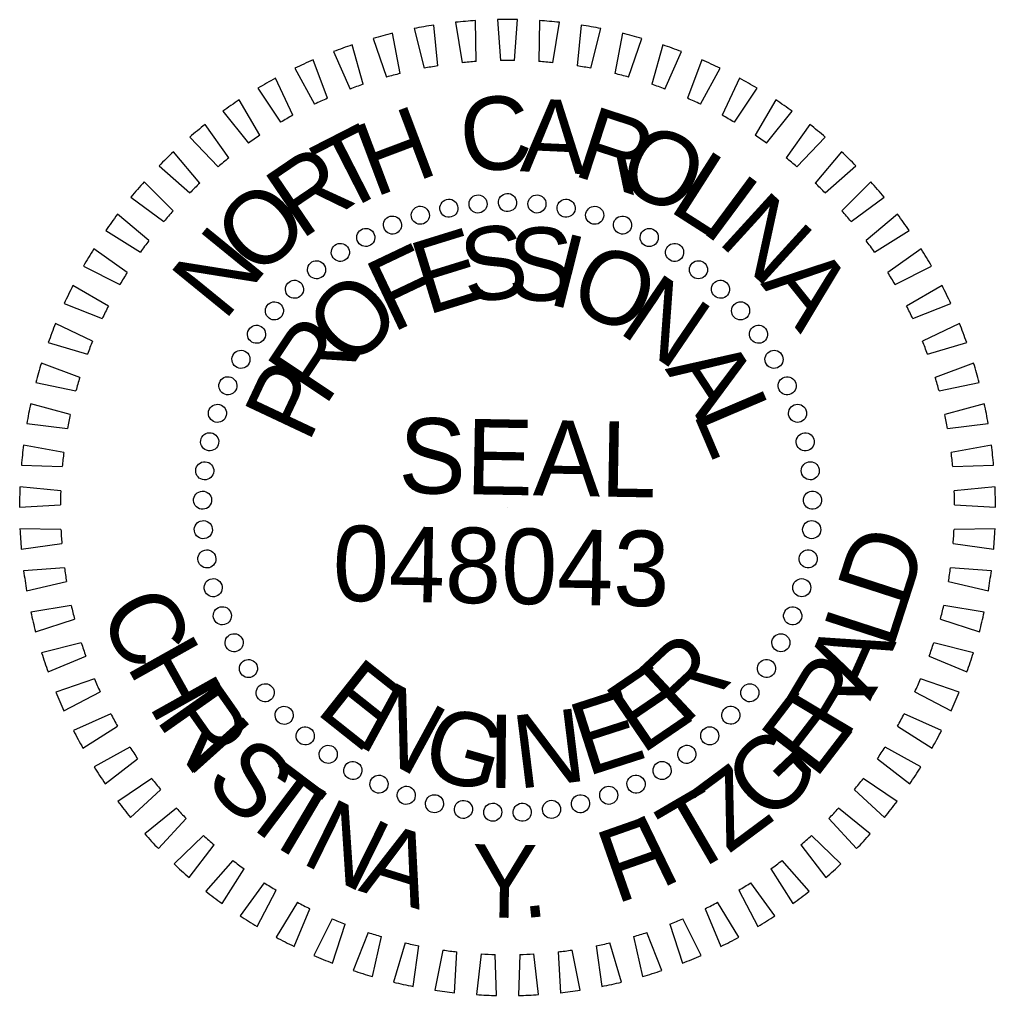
# Model space of a CAD drawing. Extents: x 2044664 to 2046614, y 755540 to 756566.
# Drawn here: x 2046310.5 to 2046390.5, y 756451.5 to 756531.5 of the extents above; entities that cross this region are included whole.
import ezdxf

# ---------------------------------------------------------------- set-up
doc = ezdxf.new("R2010")
doc.units = 0
doc.layers.add('Sheet PE Seal Cell', color=7, linetype='Continuous')

msp = doc.modelspace()

# ---------------------------------------------------------------- linework, layer by layer
at = {"layer": 'Sheet PE Seal Cell'}
for p, q in [((2046344.826, 756527.666), (2046344.499, 756531.005)), ((2046346.276, 756531.236), (2046346.813, 756527.924)), ((2046347.959, 756528.023), (2046347.92, 756531.378)), ((2046349.711, 756531.455), (2046349.961, 756528.109)), ((2046351.111, 756528.109), (2046351.361, 756531.455)), ((2046353.152, 756531.378), (2046353.114, 756528.023)), ((2046354.259, 756527.924), (2046354.796, 756531.236)), ((2046356.574, 756531.005), (2046356.247, 756527.666)), ((2046341.735, 756527.041), (2046341.122, 756530.34)), ((2046342.873, 756530.723), (2046343.693, 756527.469)), ((2046357.38, 756527.469), (2046358.199, 756530.723)), ((2046359.95, 756530.34), (2046359.338, 756527.041)), ((2046338.709, 756526.153), (2046337.815, 756529.387)), ((2046339.527, 756529.918), (2046340.623, 756526.747)), ((2046360.45, 756526.747), (2046361.546, 756529.918)), ((2046363.258, 756529.387), (2046362.364, 756526.153)), ((2046336.262, 756528.83), (2046337.626, 756525.764)), ((2046363.446, 756525.764), (2046364.811, 756528.83)), ((2046335.77, 756525.007), (2046334.602, 756528.153)), ((2046366.471, 756528.153), (2046365.302, 756525.007)), ((2046333.102, 756527.464), (2046334.725, 756524.528)), ((2046366.347, 756524.528), (2046367.97, 756527.464)), ((2046332.942, 756523.614), (2046331.507, 756526.647)), ((2046369.566, 756526.647), (2046368.131, 756523.614)), ((2046330.072, 756525.832), (2046331.942, 756523.046)), ((2046369.131, 756523.046), (2046371, 756525.832)), ((2046330.243, 756521.982), (2046328.553, 756524.881)), ((2046372.52, 756524.881), (2046370.829, 756521.982)), ((2046327.193, 756523.946), (2046329.295, 756521.331)), ((2046371.777, 756521.331), (2046373.879, 756523.946)), ((2046327.694, 756520.125), (2046325.761, 756522.867)), ((2046375.311, 756522.867), (2046373.378, 756520.125)), ((2046324.487, 756521.819), (2046326.806, 756519.394)), ((2046374.266, 756519.394), (2046376.585, 756521.819)), ((2046325.315, 756518.055), (2046323.153, 756520.621)), ((2046377.919, 756520.621), (2046375.757, 756518.055)), ((2046321.974, 756519.467), (2046324.493, 756517.251)), ((2046376.579, 756517.251), (2046379.098, 756519.467)), ((2046323.123, 756515.789), (2046320.748, 756518.159)), ((2046380.324, 756518.159), (2046377.95, 756515.789)), ((2046319.673, 756516.908), (2046322.373, 756514.917)), ((2046378.7, 756514.917), (2046381.4, 756516.908)), ((2046321.133, 756513.342), (2046318.564, 756515.5)), ((2046382.509, 756515.5), (2046379.939, 756513.342)), ((2046317.599, 756514.161), (2046320.461, 756512.409)), ((2046380.611, 756512.409), (2046383.473, 756514.161)), ((2046319.361, 756510.733), (2046316.616, 756512.662)), ((2046384.457, 756512.662), (2046381.711, 756510.733)), ((2046315.77, 756511.245), (2046318.772, 756509.746)), ((2046382.301, 756509.746), (2046385.302, 756511.245)), ((2046317.82, 756507.982), (2046314.919, 756509.668)), ((2046386.154, 756509.668), (2046383.253, 756507.982)), ((2046314.198, 756508.184), (2046317.318, 756506.947)), ((2046383.755, 756506.947), (2046386.874, 756508.184)), ((2046316.521, 756505.108), (2046313.486, 756506.539)), ((2046387.587, 756506.539), (2046384.551, 756505.108)), ((2046312.896, 756504.998), (2046316.11, 756504.035)), ((2046384.963, 756504.035), (2046388.177, 756504.998)), ((2046315.474, 756502.134), (2046312.327, 756503.298)), ((2046388.745, 756503.298), (2046385.598, 756502.134)), ((2046311.871, 756501.712), (2046315.156, 756501.029)), ((2046385.916, 756501.029), (2046389.201, 756501.712)), ((2046314.686, 756499.08), (2046311.451, 756499.969)), ((2046389.621, 756499.969), (2046386.386, 756499.08)), ((2046311.133, 756498.35), (2046314.465, 756497.952)), ((2046386.607, 756497.952), (2046389.939, 756498.35)), ((2046314.164, 756495.97), (2046310.865, 756496.578)), ((2046390.208, 756496.578), (2046386.908, 756495.97)), ((2046310.687, 756494.938), (2046314.041, 756494.827)), ((2046387.032, 756494.827), (2046390.385, 756494.938)), ((2046313.912, 756492.827), (2046310.572, 756493.149)), ((2046390.501, 756493.149), (2046387.161, 756492.827)), ((2046310.536, 756491.499), (2046313.887, 756491.677)), ((2046350.536, 756491.463), (2046350.536, 756491.463)), ((2046387.186, 756491.677), (2046390.536, 756491.499)), ((2046313.93, 756489.673), (2046310.575, 756489.707)), ((2046390.498, 756489.707), (2046387.142, 756489.673)), ((2046310.681, 756488.06), (2046314.004, 756488.526)), ((2046387.068, 756488.526), (2046390.391, 756488.06)), ((2046314.219, 756486.533), (2046310.874, 756486.278)), ((2046390.199, 756486.278), (2046386.853, 756486.533)), ((2046311.121, 756484.647), (2046314.392, 756485.396)), ((2046386.68, 756485.396), (2046389.951, 756484.647)), ((2046314.778, 756483.429), (2046311.466, 756482.888)), ((2046389.606, 756482.888), (2046386.295, 756483.429)), ((2046311.853, 756481.284), (2046315.047, 756482.311)), ((2046386.025, 756482.311), (2046389.219, 756481.284)), ((2046315.601, 756480.385), (2046312.348, 756479.561)), ((2046388.724, 756479.561), (2046385.472, 756480.385)), ((2046312.871, 756477.996), (2046315.965, 756479.295)), ((2046385.107, 756479.295), (2046388.201, 756477.996)), ((2046316.682, 756477.423), (2046313.513, 756476.322)), ((2046387.56, 756476.322), (2046384.39, 756477.423)), ((2046314.169, 756474.808), (2046317.139, 756476.368)), ((2046383.933, 756476.368), (2046386.904, 756474.808)), ((2046318.015, 756474.565), (2046314.951, 756473.195)), ((2046386.121, 756473.195), (2046383.058, 756474.565)), ((2046315.735, 756471.743), (2046318.561, 756473.553)), ((2046382.512, 756473.553), (2046385.337, 756471.743)), ((2046319.588, 756471.832), (2046316.653, 756470.204)), ((2046384.419, 756470.204), (2046381.485, 756471.832)), ((2046317.559, 756468.825), (2046320.219, 756470.87)), ((2046380.853, 756470.87), (2046383.513, 756468.825)), ((2046321.39, 756469.244), (2046318.606, 756467.37)), ((2046382.466, 756467.37), (2046379.682, 756469.244)), ((2046319.627, 756466.074), (2046322.101, 756468.34)), ((2046378.971, 756468.34), (2046381.445, 756466.074)), ((2046323.408, 756466.82), (2046320.796, 756464.714)), ((2046380.277, 756464.714), (2046377.664, 756466.82)), ((2046321.924, 756463.511), (2046324.194, 756465.981)), ((2046376.878, 756465.981), (2046379.148, 756463.511)), ((2046325.627, 756464.58), (2046323.205, 756462.257)), ((2046377.867, 756462.257), (2046375.446, 756464.58)), ((2046324.433, 756461.154), (2046326.483, 756463.811)), ((2046374.59, 756463.811), (2046376.639, 756461.154)), ((2046328.03, 756462.538), (2046325.817, 756460.015)), ((2046375.255, 756460.015), (2046373.042, 756462.538)), ((2046327.135, 756459.023), (2046328.949, 756461.846)), ((2046372.124, 756461.846), (2046373.937, 756459.023)), ((2046330.6, 756460.71), (2046328.612, 756458.007)), ((2046372.46, 756458.007), (2046370.472, 756460.71)), ((2046330.011, 756457.131), (2046331.575, 756460.1)), ((2046369.498, 756460.1), (2046371.062, 756457.131)), ((2046333.317, 756459.11), (2046331.57, 756456.246)), ((2046369.503, 756456.246), (2046367.755, 756459.11)), ((2046333.038, 756455.494), (2046334.341, 756458.586)), ((2046366.731, 756458.586), (2046368.034, 756455.494)), ((2046336.162, 756457.75), (2046334.667, 756454.746)), ((2046336.195, 756454.123), (2046337.227, 756457.315)), ((2046363.845, 756457.315), (2046364.877, 756454.123)), ((2046366.405, 756454.746), (2046364.91, 756457.75)), ((2046339.114, 756456.639), (2046337.882, 756453.518)), ((2046363.19, 756453.518), (2046361.958, 756456.639)), ((2046339.458, 756453.028), (2046340.212, 756456.298)), ((2046342.15, 756455.786), (2046341.191, 756452.57)), ((2046359.881, 756452.57), (2046358.922, 756455.786)), ((2046360.86, 756456.298), (2046361.614, 756453.028)), ((2046342.803, 756452.218), (2046343.273, 756455.54)), ((2046345.248, 756455.197), (2046344.569, 756451.911)), ((2046346.205, 756451.699), (2046346.388, 756455.049)), ((2046354.684, 756455.049), (2046354.867, 756451.699)), ((2046356.503, 756451.911), (2046355.824, 756455.197)), ((2046357.799, 756455.54), (2046358.269, 756452.218)), ((2046348.385, 756454.877), (2046347.991, 756451.545)), ((2046349.64, 756451.474), (2046349.534, 756454.827)), ((2046351.538, 756454.827), (2046351.432, 756451.474)), ((2046353.081, 756451.545), (2046352.687, 756454.877))]:
    msp.add_line(p, q, dxfattribs=at)
for radius, start, end in [(40, 98.6812, 101.04482), (40, 93.7497, 96.11332), (40, 88.81819, 91.18181), (40, 83.88668, 86.2503), (40, 78.95518, 81.3188), (40, 103.61271, 105.97633), (40, 74.02367, 76.38729), (40, 108.54422, 110.90784), (40, 69.09216, 71.45578), (40, 113.47572, 115.83934), (36.65, 94.03256, 95.83045), (36.65, 89.10105, 90.89895), (36.65, 84.16955, 85.96744), (40, 64.16066, 66.52427), (36.65, 103.89557, 105.69347), (36.65, 98.96407, 100.76196), (36.65, 79.23804, 81.03593), (36.65, 74.30653, 76.10443), (40, 118.40723, 120.77085), (36.65, 108.82708, 110.62497), (36.65, 69.37503, 71.17292), (40, 59.22915, 61.59277), (40, 123.33874, 125.70236), (36.65, 113.75859, 115.55648), (36.65, 64.44352, 66.24141), (40, 54.29764, 56.66126), (36.65, 118.69009, 120.48799), (36.65, 59.51201, 61.30991), (40, 128.27025, 130.63386), (40, 49.36614, 51.72975), (36.65, 123.6216, 125.4195), (36.65, 54.5805, 56.3784), (40, 133.20175, 135.56537), (40, 44.43463, 46.79825), (36.65, 128.55311, 130.351), (36.65, 49.649, 51.44689), (40, 138.13326, 140.49688), (40, 39.50312, 41.86674), (36.65, 133.48461, 135.28251), (36.65, 44.71749, 46.51539), (36.65, 138.41612, 140.21402), (36.65, 39.78598, 41.58388), (40, 143.06477, 145.42838), (40, 34.57162, 36.93523), (36.65, 143.34763, 145.14552), (36.65, 34.85448, 36.65237), (40, 147.99627, 150.35989), (40, 29.64011, 32.00373), (36.65, 148.27913, 150.07703), (36.65, 29.92297, 31.72087), (40, 152.92778, 155.2914), (40, 24.7086, 27.07222), (36.65, 153.21064, 155.00854), (36.65, 24.99146, 26.78936), (40, 157.85929, 160.22291), (40, 19.77709, 22.14071), (36.65, 158.14215, 159.94004), (36.65, 20.05996, 21.85785), (40, 162.79079, 165.15441), (40, 14.84559, 17.20921), (36.65, 163.07366, 164.87155), (36.65, 15.12845, 16.92634), (40, 167.7223, 170.08592), (40, 9.91408, 12.2777), (36.65, 168.00516, 169.80306), (36.65, 10.19694, 11.99484), (40, 172.65381, 175.01743), (40, 4.98257, 7.34619), (36.65, 172.93667, 174.73456), (36.65, 5.26544, 7.06333), (40, 177.58531, 179.94893), (36.65, 177.86818, 179.66607), (36.65, 0.33393, 2.13182), (40, 0.05107, 2.41469), (40, 182.51682, 184.88044), (36.65, 182.79968, 184.59758), (36.65, 355.40242, 357.20032), (40, 355.11956, 357.48318), (40, 187.44833, 189.81195), (36.65, 187.73119, 189.52908), (36.65, 350.47092, 352.26881), (40, 350.18805, 352.55167), (36.65, 192.6627, 194.46059), (36.65, 345.53941, 347.3373), (40, 192.37983, 194.74345), (40, 345.25655, 347.62017), (36.65, 197.5942, 199.3921), (36.65, 340.6079, 342.4058), (40, 197.31134, 199.67496), (40, 340.32504, 342.68866), (36.65, 202.52571, 204.3236), (36.65, 335.67639, 337.47429), (40, 202.24285, 204.60647), (40, 335.39353, 337.75715), (36.65, 207.45722, 209.25511), (36.65, 330.74489, 332.54278), (40, 207.17436, 209.53797), (40, 330.46203, 332.82564), (36.65, 212.38872, 214.18662), (36.65, 325.81338, 327.61128), (40, 212.10586, 214.46948), (40, 325.53052, 327.89414), (36.65, 217.32023, 219.11813), (36.65, 320.88187, 322.67977), (40, 217.03737, 219.40099), (40, 320.59901, 322.96263), (36.65, 222.25174, 224.04963), (36.65, 315.95037, 317.74826), (40, 221.96888, 224.33249), (36.65, 227.18324, 228.98114), (36.65, 311.01886, 312.81676), (40, 315.66751, 318.03112), (40, 226.90038, 229.264), (36.65, 232.11475, 233.91265), (36.65, 306.08735, 307.88525), (40, 310.736, 313.09962), (36.65, 237.04626, 238.84415), (36.65, 301.15585, 302.95374), (40, 231.83189, 234.19551), (40, 305.80449, 308.16811), (36.65, 241.97776, 243.77566), (36.65, 296.22434, 298.02224), (40, 236.7634, 239.12701), (36.65, 246.90927, 248.70717), (36.65, 291.29283, 293.09073), (40, 300.87299, 303.2366), (36.65, 251.84078, 253.63867), (36.65, 286.36133, 288.15922), (40, 241.6949, 244.05852), (36.65, 256.77229, 258.57018), (36.65, 281.42982, 283.22771), (40, 295.94148, 298.3051), (36.65, 261.70379, 263.50169), (36.65, 276.49831, 278.29621), (40, 246.62641, 248.99003), (36.65, 266.6353, 268.43319), (36.65, 271.56681, 273.3647), (40, 291.00997, 293.37359), (40, 251.55792, 253.92154), (40, 286.07846, 288.44208), (40, 256.48942, 258.85304), (40, 281.14696, 283.51058), (40, 261.42093, 263.78455), (40, 276.21545, 278.57907), (40, 266.35244, 268.71606), (40, 271.28394, 273.64756)]:
    msp.add_arc((2046350.536, 756491.463), radius, start, end, dxfattribs=at)
for centre, major_axis in [((2046345.733, 756515.998), (-0.193, 0.717)), ((2046348.123, 756516.347), (-0.123, 0.732)), ((2046350.536, 756516.463), (-0.052, 0.741)), ((2046352.949, 756516.347), (0.02, 0.742)), ((2046355.339, 756515.998), (0.091, 0.737)), ((2046343.388, 756515.42), (-0.261, 0.695)), ((2046357.685, 756515.42), (0.162, 0.724)), ((2046341.109, 756514.618), (-0.327, 0.666)), ((2046359.964, 756514.618), (0.231, 0.705)), ((2046338.918, 756513.6), (-0.39, 0.632)), ((2046362.154, 756513.6), (0.298, 0.68)), ((2046336.836, 756512.375), (-0.449, 0.591)), ((2046364.236, 756512.375), (0.363, 0.648)), ((2046334.882, 756510.955), (-0.504, 0.545)), ((2046366.191, 756510.955), (0.423, 0.61)), ((2046333.073, 756509.353), (-0.554, 0.494)), ((2046367.999, 756509.353), (0.48, 0.566)), ((2046331.428, 756507.585), (-0.599, 0.438)), ((2046369.644, 756507.585), (0.533, 0.517)), ((2046329.962, 756505.665), (-0.639, 0.378)), ((2046371.111, 756505.665), (0.58, 0.463)), ((2046328.687, 756503.613), (-0.672, 0.315)), ((2046372.385, 756503.613), (0.622, 0.405)), ((2046327.616, 756501.448), (-0.7, 0.248)), ((2046373.456, 756501.448), (0.658, 0.343)), ((2046326.76, 756499.189), (-0.72, 0.18)), ((2046374.313, 756499.189), (0.688, 0.278)), ((2046326.125, 756496.858), (-0.734, 0.109)), ((2046374.947, 756496.858), (0.712, 0.21)), ((2046325.718, 756494.477), (-0.741, 0.038)), ((2046375.354, 756494.477), (0.729, 0.141)), ((2046325.543, 756492.068), (-0.742, -0.034)), ((2046375.529, 756492.068), (0.739, 0.07)), ((2046325.602, 756489.653), (-0.735, -0.105)), ((2046375.471, 756489.653), (0.742, -0.002)), ((2046325.893, 756487.255), (-0.721, -0.176)), ((2046375.179, 756487.255), (0.739, -0.074)), ((2046326.414, 756484.896), (-0.701, -0.245)), ((2046374.658, 756484.896), (0.728, -0.145)), ((2046327.161, 756482.598), (-0.674, -0.311)), ((2046373.912, 756482.598), (0.711, -0.214)), ((2046328.126, 756480.384), (-0.641, -0.375)), ((2046372.947, 756480.384), (0.687, -0.282)), ((2046329.299, 756478.272), (-0.602, -0.435)), ((2046371.773, 756478.272), (0.656, -0.347)), ((2046330.672, 756476.284), (-0.557, -0.491)), ((2046370.401, 756476.284), (0.62, -0.408)), ((2046332.229, 756474.438), (-0.507, -0.542)), ((2046368.843, 756474.438), (0.578, -0.466)), ((2046333.958, 756472.751), (-0.452, -0.589)), ((2046367.114, 756472.751), (0.53, -0.52)), ((2046335.842, 756471.238), (-0.393, -0.63)), ((2046365.231, 756471.238), (0.477, -0.569)), ((2046337.862, 756469.914), (-0.331, -0.665)), ((2046363.21, 756469.914), (0.42, -0.612)), ((2046340.001, 756468.792), (-0.265, -0.693)), ((2046361.071, 756468.792), (0.359, -0.65)), ((2046342.238, 756467.881), (-0.197, -0.716)), ((2046358.834, 756467.881), (0.295, -0.681)), ((2046344.553, 756467.19), (-0.127, -0.731)), ((2046356.519, 756467.19), (0.227, -0.707)), ((2046346.924, 756466.726), (-0.056, -0.74)), ((2046349.328, 756466.493), (0.016, -0.742)), ((2046351.744, 756466.493), (0.087, -0.737)), ((2046354.148, 756466.726), (0.158, -0.725))]:
    msp.add_ellipse(centre, major_axis=major_axis, ratio=0.999708, dxfattribs=at)

# ---------------------------------------------------------------- texts
for s, height, rotation, p in [('C', 6, 6.29227, (2046346.971, 756518.834)), ('A', 6, 357.40789, (2046351.53, 756519.029)), ('H', 6, 20.66115, (2046339.624, 756516.863)), ('R', 6, 341.92066, (2046355.75, 756518.746)), ('T', 6, 27.0543, (2046336.838, 756515.481)), ('O', 6, 334.63141, (2046359.208, 756517.886)), ('R', 6, 34.15123, (2046333.59, 756513.342)), ('L', 6, 327.43113, (2046363.612, 756515.869)), ('I', 6, 323.44346, (2046366.206, 756514.225)), ('O', 6, 41.81383, (2046329.993, 756510.133)), ('N', 6, 317.60701, (2046367.639, 756513.248)), ('N', 6, 50.83361, (2046327.305, 756506.651)), ('E', 6, 17.18467, (2046343.925, 756507.209)), ('S', 6, 8.38554, (2046347.179, 756508.148)), ('S', 6, 0.00536, (2046350.578, 756508.417)), ('I', 6, 345.84544, (2046353.664, 756508.2)), ('F', 6, 25.41188, (2046341.066, 756505.748)), ('O', 6, 337.45556, (2046355.324, 756507.881)), ('A', 6, 308.67669, (2046371.23, 756509.805)), ('O', 6, 44.35955, (2046337.701, 756502.668)), ('N', 6, 325.7421, (2046359.48, 756505.9)), ('R', 6, 56.28583, (2046335.559, 756499.647)), ('A', 6, 303.22173, (2046363.41, 756502.815)), ('P', 6, 64.79309, (2046334.211, 756496.648)), ('L', 6, 293.08866, (2046365.699, 756499.245)), ('SEAL', 6.1836, 359, (2046341.571, 756492.656)), ('048043', 6.1855, 359, (2046336.168, 756483.83)), ('D', 6, 72.05207, (2046383.17, 756483.075)), ('C', 6, 299.23607, (2046316.886, 756482.734)), ('L', 6, 72.05207, (2046382.082, 756479.715)), ('H', 6, 299.23607, (2046319.245, 756478.52)), ('R', 6, 42.99767, (2046364.936, 756473.446)), ('A', 6, 65.93591, (2046380.263, 756475.555)), ('E', 6, 321.57434, (2046334.678, 756474.703)), ('R', 6, 59.11353, (2046378.161, 756472.137)), ('E', 6, 34.24466, (2046361.529, 756471.159)), ('R', 6, 305.06391, (2046321.621, 756474.128)), ('N', 6, 331.42786, (2046338.007, 756472.098)), ('E', 6, 17.84102, (2046357.017, 756469.399)), ('E', 6, 52.53895, (2046375.765, 756469.101)), ('G', 6, 343.9576, (2046343.232, 756469.658)), ('N', 6, 6.99182, (2046351.398, 756468.397)), ('I', 6, 311.88628, (2046323.886, 756470.816)), ('I', 6, 359.54226, (2046348.878, 756468.499)), ('G', 6, 43.54841, (2046371.959, 756465.434)), ('S', 6, 316.25139, (2046325.536, 756468.848)), ('T', 6, 322.97052, (2046328.355, 756466.078)), ('Z', 6, 36.58149, (2046368.642, 756463.027)), ('I', 6, 329.33861, (2046331.309, 756463.774)), ('T', 6, 30.2134, (2046365.376, 756461.195)), ('N', 6, 333.70371, (2046333.473, 756462.391)), ('F', 6, 19.33566, (2046359.395, 756458.939)), ('I', 6, 25.84829, (2046363.028, 756460.153)), ('A', 6, 342.69426, (2046338.227, 756460.082)), ('Y', 6, 359.06471, (2046347.574, 756457.885)), ('.', 6, 6.17617, (2046351.755, 756457.776))]:
    msp.add_text(s, height=height, rotation=rotation, dxfattribs=at).set_placement(p)

doc.saveas('drawing.dxf')
